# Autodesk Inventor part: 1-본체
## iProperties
Created: 2014-11
Part Number: 1-본체
Document SubType Name: Modeling
Designer: elite
Density: 2.71 g/cm^3
Material: 알루미늄-6061
Mass: 2877.28 g
Surface Area: 2084.28 cm^2
Volume: 1061.73 cm^3
Author: elite
